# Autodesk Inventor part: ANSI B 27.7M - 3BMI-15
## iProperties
Created: 2007-11
Part Number: ANSI B 27.7M - 3BMI-15
Material: Steel, Mild
Description: American National Standard Metric Tapered Retaining Rings - Basic External Series - 3BMI
Document SubType Name: Modeling
Standard: ANSI B 27.7M
Designer: CM
Standards Organization: ANSI
Language: en-US
Size Designation: 3BMI-15
Categories: <MemberInstance><Categories><Category DisplayName="Shaft Parts" InternalName="7f7aeb1f-a693-4053-b835-cee3144e0d98" Mnemonic="SHFT"><Category DisplayName="Circl
Density: 7.86 g/cm^3
Mass: 0.381498 g
Surface Area: 1.8958 cm^2
Volume: 0.0485366 cm^3
IsCustomPart: 0
Author: CM
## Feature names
1. Extrusion1
2. Hole1
3. Hole2
